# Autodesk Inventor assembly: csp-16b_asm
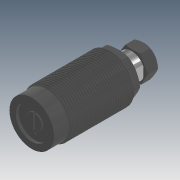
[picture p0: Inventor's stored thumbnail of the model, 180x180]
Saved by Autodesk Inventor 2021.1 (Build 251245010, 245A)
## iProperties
Created: 2019-04
Part Number: csp-16b_asm
Description: STEP AP214
Document SubType Name: Assembly
Designer: user
Sending System: SolidWorks 2016
Preprocessor: SwSTEP 2.0
Title: csp-16b_asm.STEP
Revision Number: ÈÎºÎ
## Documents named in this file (8)
- D:\Vault_2016\Projekty\Clamptek\Hydraulic\Dociski Hydrauliczne\Podporowe\CSP-16\Inventor\CSP-16B\csp-16b_asm.iam
- D:\Vault_2016\Projekty\Clamptek\Hydraulic\Dociski Hydrauliczne\Podporowe\CSP-16\Inventor\CSP-16B\CSP-16HG.ipt
- D:\Vault_2016\Projekty\Clamptek\Hydraulic\Dociski Hydrauliczne\Podporowe\CSP-16\Inventor\CSP-16B\CSP-16DG.ipt
- D:\Vault_2016\Projekty\Clamptek\Hydraulic\Dociski Hydrauliczne\Podporowe\CSP-16\Inventor\CSP-16B\M4X10_1.ipt
- D:\Vault_2016\Projekty\Clamptek\Hydraulic\Dociski Hydrauliczne\Podporowe\CSP-16\Inventor\CSP-16B\CSP-16HSG_1.ipt
- D:\Vault_2016\Projekty\Clamptek\Hydraulic\Dociski Hydrauliczne\Podporowe\CSP-16\Inventor\CSP-16B\CSP-16BT_1.ipt
- D:\Vault_2016\Projekty\Clamptek\Hydraulic\Dociski Hydrauliczne\Podporowe\CSP-16\Inventor\CSP-16B\CSP-16LS_1.ipt
- D:\Vault_2016\Projekty\Clamptek\Hydraulic\Dociski Hydrauliczne\Podporowe\CSP-16\Inventor\CSP-16B\CP-16DP_1.ipt
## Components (7 placed, 7 different names)
1. CSP-16HG_1
2. CSP-16DG_2
3. M4X10_1_3
4. CSP-16HSG_1_4
5. CSP-16BT_1_5
6. CSP-16LS_1_6
7. CP-16DP_1_7
